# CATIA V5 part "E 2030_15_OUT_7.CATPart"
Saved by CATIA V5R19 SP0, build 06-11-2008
Material "Plastic": density 1200 kg/m3, Young's modulus 2.2e+09 Pa, Poisson ratio 0.38, thermal expansion 6.84e-05 1/K
Bounding box of the stored display mesh (mm): x 37.75 to 52.85, y -30.19 to -15.11, z -2 to 0
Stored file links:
  G:\UTB\Kombinované\Bakalářská práce\Catia\FORMA\E 2030_15_OUT_7.CATPart
  D:\Aplikace\CATIA\Nová složka\win_b64\startup\materials\Catalog.CATMaterial
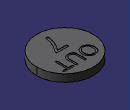
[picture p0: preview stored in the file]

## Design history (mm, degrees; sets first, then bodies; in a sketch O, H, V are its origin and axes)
Body1 "E 2030_15_OUT_1-8" (main body)
  Solid1: solid without history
